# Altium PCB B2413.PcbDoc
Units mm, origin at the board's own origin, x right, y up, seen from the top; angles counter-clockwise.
Board outline 20.33 x 34.06 mm, 4 copper layers (Top Layer, Internal 1, Internal 2, Bottom Layer), stack 1.235 mm thick; 78 components, 60 nets, 384 pads, 246 vias.
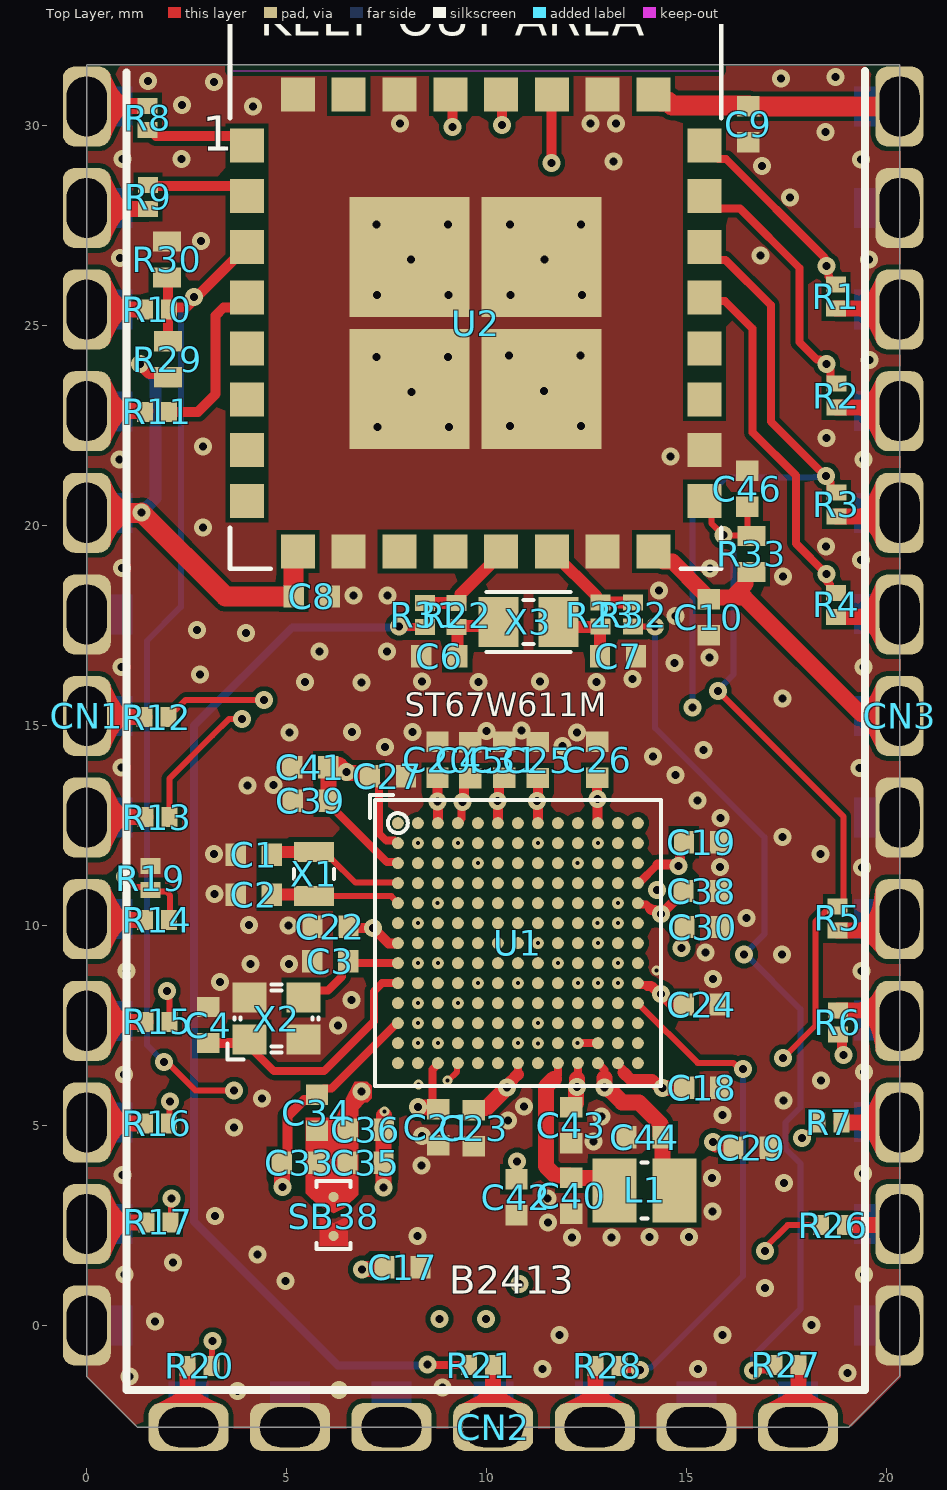
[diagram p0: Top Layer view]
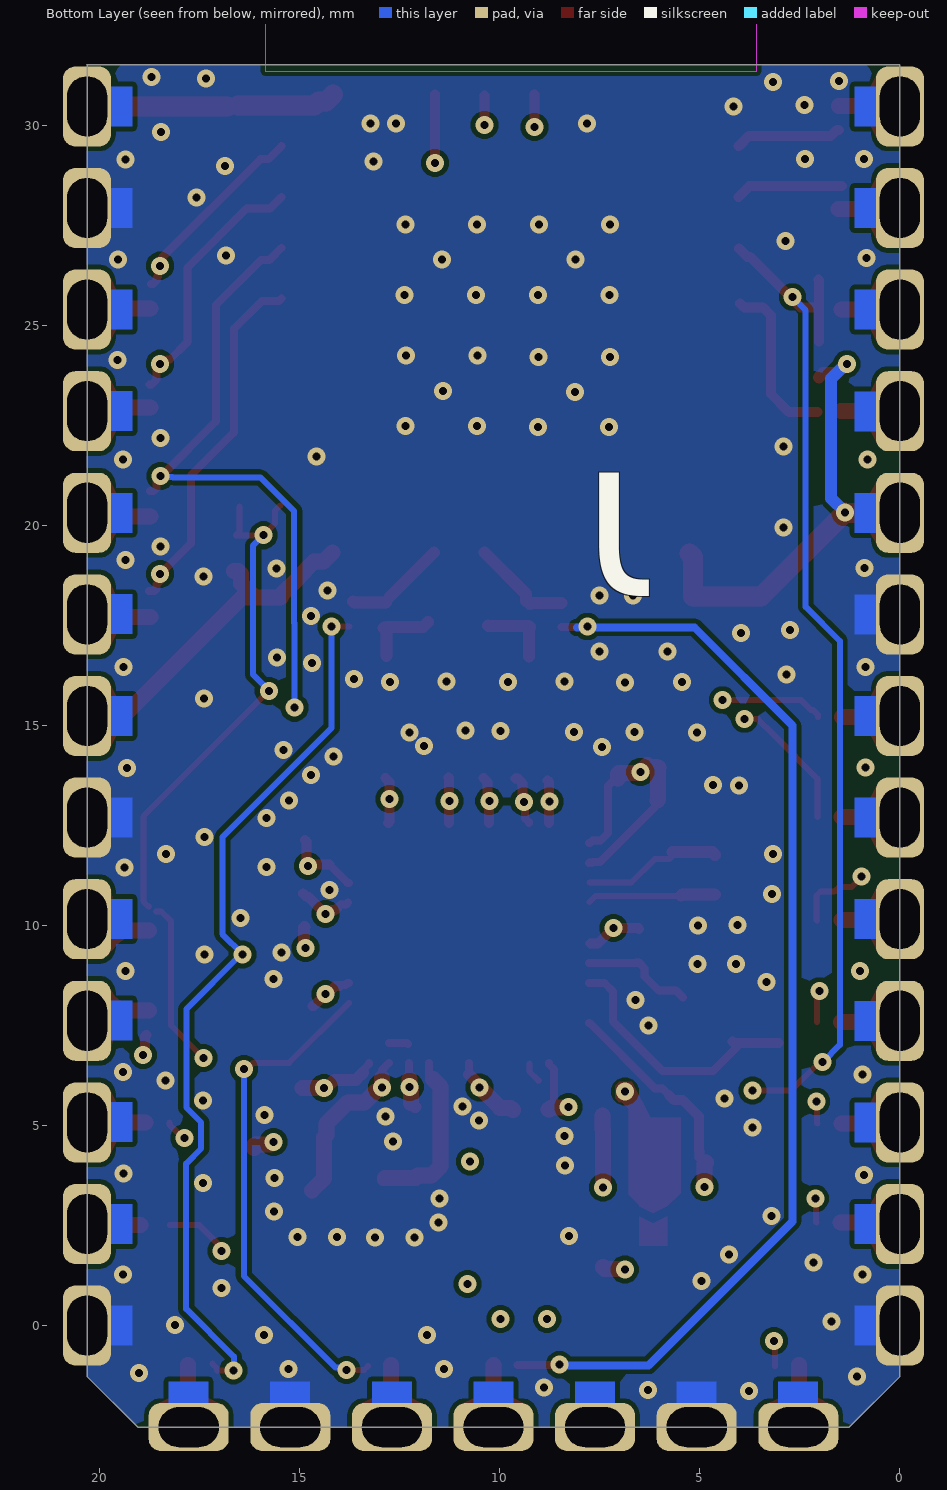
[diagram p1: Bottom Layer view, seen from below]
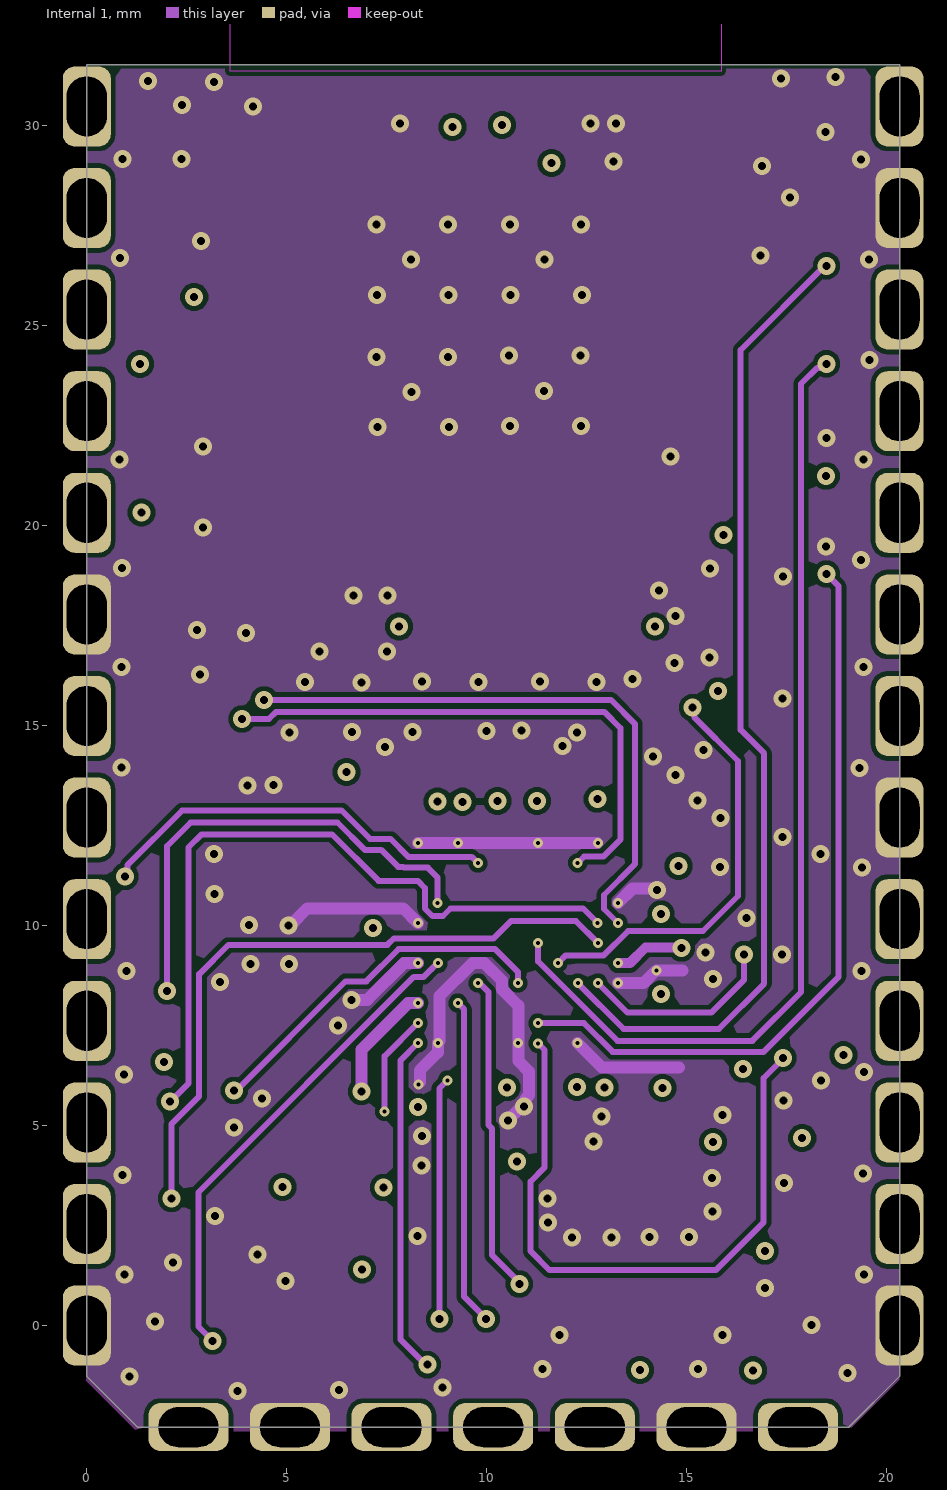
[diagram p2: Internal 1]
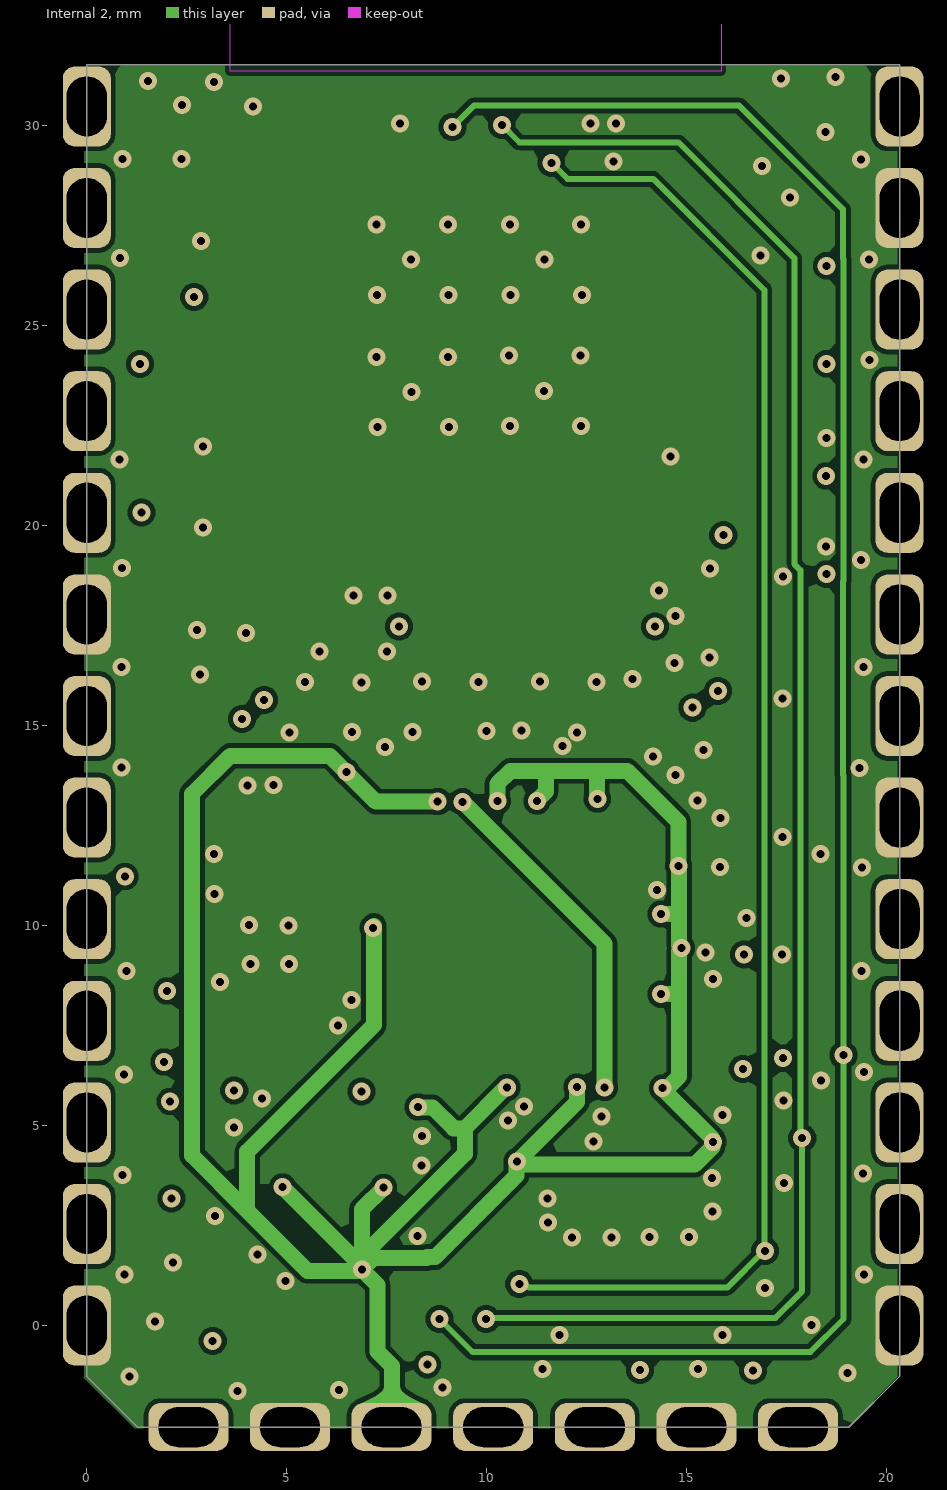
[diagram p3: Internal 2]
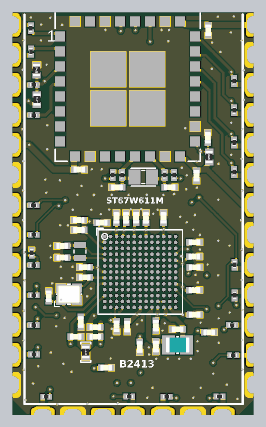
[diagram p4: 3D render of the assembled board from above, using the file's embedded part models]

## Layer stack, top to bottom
Top Solder: solder mask 0.0178, Solder Resist, Dk 3.2
Top Layer: signal copper 0.0406
Dielectric 1: core 0.0762, FR-4, Dk 3.7
Internal 1: signal copper 0.0305
Dielectric 3: prepreg 0.94, Dk 4.5
Internal 2: signal copper 0.0305
Dielectric 2: core 0.0762, Dk 3.7
Bottom Layer: signal copper 0.0406
Bottom Solder: solder mask 0.0178, Solder Resist, Dk 4.2

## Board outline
0,-1.27 1.27,-2.54 19.05,-2.54 20.32,-1.27 20.32,31.517 20.329,31.52 0,31.52 0,31.517

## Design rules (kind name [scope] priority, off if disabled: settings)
Clearance "RF Path 4" [InNet('NetJ1_1') vs InNet('GND')] p1: gap=0.18 ignorepadtopadclearanceinfootprint=FALSE
Clearance [All] p2: gap=0.12 ignorepadtopadclearanceinfootprint=FALSE
ComponentClearance [All] p1: gap=0.2 collisioncheckmode=3 verticalgap=0.2 showdistances=FALSE
HoleSize [All] p1: absolutevalues=TRUE maxlimit=10 minlimit=0.025 maxpercent=80.000 minpercent=20.000
HoleToHoleClearance [All] p1: gap=0.127 allowstackedmicrovias=TRUE
MinimumSolderMaskSliver [All] p1: minsoldermaskwidth=0.1
PlaneConnect [All] p1: planeconnectstyle=Relief reliefexpansion=0.508 reliefentries=4 reliefconductorwidth=0.21 reliefairgap=0.21
PolygonConnect Path_RF [InNet('NetC12_2')] p1: connectstyle=Direct reliefconductorwidth=0.254 reliefentries=4 polygonreliefangle="90 Angle" airgapwidth=0.254
PolygonConnect PolygonConnect_via [IsVia] p2: connectstyle=Direct reliefconductorwidth=0.254 reliefentries=4 polygonreliefangle="90 Angle" airgapwidth=0.254
PolygonConnect General [All] p3: connectstyle=Direct reliefconductorwidth=0.2 reliefentries=4 polygonreliefangle="90 Angle" airgapwidth=0.2
RoutingVias [All] p1: holewidth=0.3 width=0.8 viastyle="Through Hole" minholewidth=0.1 minwidth=0.25 maxholewidth=3.5 maxwidth=6.5
SilkToSilkClearance [All] p1 off: silktosilkclearance=0.2
SilkToSolderMaskClearance [IsPad] p1 off: minsilkscreentomaskgap=0.2 clearancetoexposedcopper=TRUE
SolderMaskExpansion [All] p1: expansion=0.102 istentingtop=FALSE
Width [All] p1: maxlimit=6 minlimit=0.1 preferedwidth=0.3 minimp=50.000000 maximp=50.000000 favimp=50.000000
23 further rules are at their usual default settings.

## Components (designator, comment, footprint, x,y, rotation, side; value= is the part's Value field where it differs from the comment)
C1 "Capacitor" C0402 4.17,11.769 r0 top value=1.8pF
C2 "Capacitor" C0402 4.172,10.774 r0 top value=1.8pF
C3 "Capacitor" C0402 6.086,9.11 r0 top value=6.8pF
C4 "Capacitor" C0402 3.036,7.514 r270 top value=6.8pF
C6 "Capacitor" C0402 8.817,16.729 r180 top value=5.1pF
C7 "Capacitor" C0402 13.282,16.734 r180 top value=5.1pF
C8 "Capacitor" C0402 5.621,18.227 r0 top value=10uF
C9 "Capacitor" C0402 16.542,30.033 r270 top value=10uF
C10 "Capacitor" C0402 15.548,17.705 r90 top value=10uF
C17 "Capacitor" C0402 7.894,1.455 r180 top value=10uF
C18 "Capacitor" C0402 15.388,5.943 r180 top value=100nF
C19 "Capacitor" C0402 15.381,12.079 r180 top value=100nF
C20 "Capacitor" C0402 8.769,14.142 r270 top value=100nF
C21 "Capacitor" C0402 8.786,4.956 r90 top value=100nF
C22 "Capacitor" C0402 6.093,9.971 r0 top value=100nF
C23 "Capacitor" C0402 9.679,4.936 r90 top value=100nF
C24 "Capacitor" C0402 15.376,8.026 r180 top value=100nF
C25 "Capacitor" C0402 11.27,14.138 r270 top value=100nF
C26 "Capacitor" C0402 12.759,14.145 r270 top value=100nF
C27 "Capacitor" C0402 7.53,13.732 r180 top value=100nF
C29 "Capacitor" C0402 16.618,4.449 r180 top value=4.7uF
C30 "Capacitor" C0402 15.395,9.963 r180 top value=100nF
C31 "Capacitor" C0402 10.435,14.145 r270 top value=100nF
C33 "Capacitor" C0402 5.328,4.073 r180 top value=1uF
C34 "Capacitor" C0402 5.755,5.322 r90 top value=100nF
C35 "Capacitor" C0402 6.968,4.071 r0 top value=1uF
C36 "Capacitor" C0402 6.972,4.891 r0 top value=100nF
C38 "Capacitor" C0402 15.369,10.863 r180 top value=100nF
C39 "Capacitor" C0402 5.6,13.116 r0 top value=100nF
C40 "Capacitor" C0402 12.115,3.245 r90 top value=100pF
C41 "Capacitor" C0402 5.588,13.953 r0 top value=10uF
C42 "Capacitor" C0402 10.743,3.208 r90 top value=10uF
C43 "Capacitor" C0402 12.113,5.011 r90 top value=100nF
C44 "Capacitor" C0402 13.944,4.706 r0 top value=2.2uF
C45 "Capacitor" C0402 9.588,14.137 r270 top value=2.2uF
C46 "Capacitor" C0402 16.51,20.92 r270 top value=100nF
CART-1 "Comment" Sheetbox_6L2S 32.282,-5.454 r0 top
CN1 "" STAMPS_HOLES_X13 0,2.54 r0 top
CN2 "" Stamps_holes_x7 2.532,-2.577 r0 top
CN3 "" STAMPS_HOLES_X13 20.32,27.94 r180 top
Designator1 "Comment" PCB_SPECIFICATIONS 32.657,17.871 r0 top
L1 "Inductor" L0805_H0P9 13.948,3.381 r0 top value=2.2uH
R1 "Resistor" R0201_H0P23 18.731,25.726 r270 top value=0R
R2 "Resistor" R0201_H0P23 18.738,23.247 r270 top value=0R
R3 "Resistor" R0201_H0P23 18.74,20.529 r270 top value=0R
R4 "Resistor" R0201_H0P23 18.733,18.017 r270 top value=0R
R5 "Resistor" R0201_H0P23 18.77,10.177 r270 top value=0R
R6 "Resistor" R0201_H0P23 18.779,7.58 r90 top value=0R
R7 "Resistor" R0201_H0P23 18.565,5.071 r0 top value=0R
R8 "Resistor" R0201_H0P23 1.521,30.195 r270 top value=0R
R9 "Resistor" R0201_H0P23 1.532,28.215 r90 top value=0R
R10 "Resistor" R0201_H0P23 1.758,25.407 r0 top value=0R
R11 "Resistor" R0201_H0P23 1.757,22.84 r0 top value=0R
R12 "Resistor" R0201_H0P23 1.745,15.211 r0 top value=0R
R13 "Resistor" R0201_H0P23 1.764,12.708 r0 top value=0R
R14 "Resistor" R0201_H0P23 1.757,10.134 r0 top value=0R
R15 "Resistor" R0201_H0P23 1.769,7.593 r0 top value=0R
R16 "Resistor" R0201_H0P23 1.759,5.056 r0 top value=0R
R17 "Resistor" R0201_H0P23 1.788,2.579 r0 top value=0R
R19 "Resistor" R0201_H0P23 1.597,11.186 r90 top value=100K
R20 "Resistor" R0201_H0P23 2.819,-1.005 r0 top value=0R
R21 "Resistor" R0201_H0P23 9.859,-0.987 r180 top value=0R
R22 "Resistor" R0201_H0P23 9.248,17.76 r270 top value=NM
R23 "Resistor" R0201_H0P23 12.845,17.773 r270 top value=NM
R26 "Resistor" R0201_H0P23 18.661,2.512 r0 top value=0R
R27 "Resistor" R0201_H0P23 17.492,-0.981 r180 top value=0R
R28 "Resistor" R0201_H0P23 13.021,-1.006 r0 top value=0R
R29 "Resistor" R0402 2.027,24.156 r270 top value=NM
R30 "Resistor" R0402 2.01,26.653 r270 top value=33K
R31 "Resistor" R0201_H0P23 8.459,17.768 r90 top value=0R
R32 "Resistor" R0201_H0P23 13.652,17.773 r270 top value=0R
R33 "Resistor" R0402 16.62,19.289 r270 top value=33K
SB38 "SB_ON" SOLDER-BRIDGE_R0402-0R 6.17,2.767 r270 top value=0R
U1 "STM32U575AII6QU" ICC_UFBGA169_7X7_P050 10.778,9.562 r0 top value=STM32U575AII6Q
U2 "STM32WW611MNA6BT" STM32WW611MNA6B 4.036,29.502 r0 top
X1 "XTAL_2_PINS" CRY_NX1610SE_2P 5.681,11.287 r90 top value=32.768kHz
X2 "XTAL_4_PINS" CRY_NX2016SA_4P 4.746,7.673 r0 top value=16MHz
X3 "XTAL_2_PINS" CRY_NX2012SA_2P 11.043,17.593 r180 top value=32.768KHz

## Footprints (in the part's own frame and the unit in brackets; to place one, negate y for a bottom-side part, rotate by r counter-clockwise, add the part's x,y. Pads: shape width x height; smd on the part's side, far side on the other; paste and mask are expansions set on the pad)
C0402 [mm]
  rect 0.51x0.56 smd mask+0.05: 1(-0.45,0) 2(0.45,0)
  body extent -0.5,-0.3 0.5,0.3, height 0.4
CRY_NX1610SE_2P [mm] "MCD-02291"
  rect 0.5x1 smd mask+0.05: 1(-0.55,0) 2(0.55,0)
  silkscreen extent -0.13,-0.5 0.13,0.5, body extent -0.8,-0.5 0.8,0.5, height 0.45
CRY_NX2012SA_2P [mm]
  rect 1x1.25 smd mask+0.05: 1(-0.75,0) 2(0.75,0)
  silkscreen extent -1.05,-0.75 1.05,0.75, body extent -1.05,-0.63 1.05,0.63, height 0.6
CRY_NX2016SA_4P [mm]
  rect 0.85x0.75 smd mask+0.05: 1(-0.675,-0.525) 2(0.675,-0.525) 3(0.675,0.525) 4(-0.675,0.525)
  silkscreen extent -1.22,-1.02 1.05,0.85, body extent -1.05,-0.85 1.05,0.85, height 0.7
ICC_UFBGA169_7X7_P050 [mm]
  round 0.3 smd mask+0.05: A1(-3,3) A2(-2.5,3) A3(-2,3) A4(-1.5,3) A5(-1,3) A6(-0.5,3) A7(0,3) A8(0.5,3) A9(1,3) A10(1.5,3) A11(2,3) A12(2.5,3) A13(3,3) B1(-3,2.5) B2(-2.5,2.5) B3(-2,2.5) B4(-1.5,2.5) B5(-1,2.5) B6(-0.5,2.5) B7(0,2.5) B8(0.5,2.5) B9(1,2.5) B10(1.5,2.5) B11(2,2.5) B12(2.5,2.5) B13(3,2.5) C1(-3,2) C2(-2.5,2) C3(-2,2) C4(-1.5,2) C5(-1,2) C6(-0.5,2) C7(0,2) C8(0.5,2) C9(1,2) C10(1.5,2) C11(2,2) C12(2.5,2) C13(3,2) D1(-3,1.5) D2(-2.5,1.5) D3(-2,1.5) D4(-1.5,1.5) D5(-1,1.5) D6(-0.5,1.5) D7(0,1.5) D8(0.5,1.5) D9(1,1.5) D10(1.5,1.5) D11(2,1.5) D12(2.5,1.5) D13(3,1.5) E1(-3,1) E2(-2.5,1) E3(-2,1) E4(-1.5,1) E5(-1,1) E6(-0.5,1) E7(0,1) E8(0.5,1) E9(1,1) E10(1.5,1) E11(2,1) E12(2.5,1) E13(3,1) F1(-3,0.5) F2(-2.5,0.5) F3(-2,0.5) F4(-1.5,0.5) F5(-1,0.5) F6(-0.5,0.5) F7(0,0.5) F8(0.5,0.5) F9(1,0.5) F10(1.5,0.5) F11(2,0.5) F12(2.5,0.5) F13(3,0.5) G1(-3,0) G2(-2.5,0) G3(-2,0) G4(-1.5,0) G5(-1,0) G6(-0.5,0) G7(0,0) G8(0.5,0) G9(1,0) G10(1.5,0) G11(2,0) G12(2.5,0) G13(3,0) H1(-3,-0.5) H2(-2.5,-0.5) H3(-2,-0.5) H4(-1.5,-0.5) H5(-1,-0.5) H6(-0.5,-0.5) H7(0,-0.5) H8(0.5,-0.5) H9(1,-0.5) H10(1.5,-0.5) H11(2,-0.5) H12(2.5,-0.5) H13(3,-0.5) J1(-3,-1) J2(-2.5,-1) J3(-2,-1) J4(-1.5,-1) J5(-1,-1) J6(-0.5,-1) J7(0,-1) J8(0.5,-1) J9(1,-1) J10(1.5,-1) J11(2,-1) J12(2.5,-1) J13(3,-1) K1(-3,-1.5) K2(-2.5,-1.5) K3(-2,-1.5) K4(-1.5,-1.5) K5(-1,-1.5) K6(-0.5,-1.5) K7(0,-1.5) K8(0.5,-1.5) K9(1,-1.5) K10(1.5,-1.5) K11(2,-1.5) K12(2.5,-1.5) K13(3,-1.5) L1(-3,-2) L2(-2.5,-2) L3(-2,-2) L4(-1.5,-2) L5(-1,-2) L6(-0.5,-2) L7(0,-2) L8(0.5,-2) L9(1,-2) L10(1.5,-2) L11(2,-2) L12(2.5,-2) L13(3,-2) M1(-3,-2.5) M2(-2.5,-2.5) M3(-2,-2.5) M4(-1.5,-2.5) M5(-1,-2.5) M6(-0.5,-2.5) M7(0,-2.5) M8(0.5,-2.5) M9(1,-2.5) M10(1.5,-2.5) M11(2,-2.5) M12(2.5,-2.5) M13(3,-2.5) N1(-3,-3) N2(-2.5,-3) N3(-2,-3) N4(-1.5,-3) N5(-1,-3) N6(-0.5,-3) N7(0,-3) N8(0.5,-3) N9(1,-3) N10(1.5,-3) N11(2,-3) N12(2.5,-3) N13(3,-3)
  silkscreen extent -3.7,-3.57 3.57,3.7, body extent -3.57,-3.57 3.57,3.57, height 0.61
L0805_H0P9 [mm]
  rect 1.1x1.6 smd mask+0.05: 1(-0.75,0) 2(0.75,0)
  silkscreen extent -0.08,-0.7 0.08,0.7, body extent -1.07,-0.7 1.07,0.7, height 1.2
PCB_SPECIFICATIONS [mm]
R0201_H0P23 [mm]
  rect 0.4x0.5 smd mask+0.05: 1(-0.3,0) 2(0.3,0)
  body extent -0.32,-0.17 0.32,0.17, height 0.26
R0402 [mm]
  rect 0.51x0.7 smd mask+0.05: 1(-0.45,0) 2(0.45,0)
  body extent -0.52,-0.3 0.52,0.3, height 0.4
Sheetbox_6L2S [mil] "Sheetbox 6 layers / 2 silkscreens"
  round 20 on Mech16: 1(813.5,208.05) 1(2736.63,208.05)
SOLDER-BRIDGE_R0402-0R [mil] "MCD-01619"
  round 10 smd paste-393.7: 1(-17.72,0) 2(20.67,0)
  Top Layer region: 1.48,13.78 8.37,0 1.48,-13.78 30.51,-13.78 30.51,13.78
  Top Layer region: -30.51,-13.78 -30.51,13.78 -8.37,13.78 -1.48,0 -8.37,-13.78
  silkscreen extent -33,-17 33,17, body extent -20,-12 20,12, height 14
Stamps_holes_x7 [mm]
  rrect50% 2x1.2 hole 1 slot 1.5 at 0 deg mask+0.102: 1(0.008,0.037) 2(2.548,0.037) 3(5.088,0.037) 4(7.628,0.037) 5(10.168,0.037) 6(12.708,0.037) 7(15.248,0.037)
  Bottom Layer region: 8.132,-0.024 8.132,1.176 7.132,1.176 7.132,-0.024
  Bottom Layer region: 5.592,-0.024 5.592,1.176 4.592,1.176 4.592,-0.024
  Bottom Layer region: 3.052,-0.025 3.052,1.175 2.052,1.175 2.052,-0.025
  Bottom Layer region: 0.512,-0.024 0.512,1.176 -0.488,1.176 -0.488,-0.024
  Bottom Layer region: 10.672,-0.024 10.672,1.176 9.672,1.176 9.672,-0.024
  Bottom Layer region: 13.212,-0.024 13.212,1.176 12.212,1.176 12.212,-0.024
  Bottom Layer region: 15.752,-0.024 15.752,1.176 14.752,1.176 14.752,-0.024
STAMPS_HOLES_X13 [mm]
  rrect50% 1.2x2 hole 1 slot 1.5 at 90 deg mask+0.102: 1(0,27.94) 2(0,25.4) 3(0,22.86) 4(0,20.32) 5(0,17.78) 6(0,15.24) 7(0,12.7) 8(0,10.16) 9(0,7.62) 10(0,5.08) 11(0,2.54) 12(0,0) 13(0,-2.54)
  Bottom Layer region: -0.062,-3.04 1.138,-3.04 1.138,-2.04 -0.062,-2.04
  Bottom Layer region: -0.062,19.817 1.138,19.817 1.138,20.817 -0.062,20.817
  Bottom Layer region: -0.062,22.357 1.138,22.357 1.138,23.357 -0.062,23.357
  Bottom Layer region: -0.062,24.897 1.138,24.897 1.138,25.897 -0.062,25.897
  Bottom Layer region: -0.062,27.437 1.138,27.437 1.138,28.437 -0.062,28.437
  Bottom Layer region: -0.062,17.277 1.138,17.277 1.138,18.277 -0.062,18.277
  Bottom Layer region: -0.062,14.737 1.138,14.737 1.138,15.737 -0.062,15.737
  Bottom Layer region: -0.062,12.197 1.138,12.197 1.138,13.197 -0.062,13.197
  Bottom Layer region: -0.062,9.657 1.138,9.657 1.138,10.657 -0.062,10.657
  Bottom Layer region: -0.062,7.12 1.138,7.12 1.138,8.12 -0.062,8.12
  Bottom Layer region: -0.062,4.58 1.138,4.58 1.138,5.58 -0.062,5.58
  Bottom Layer region: -0.062,2.04 1.138,2.04 1.138,3.04 -0.062,3.04
  Bottom Layer region: -0.062,-0.5 1.138,-0.5 1.138,0.5 -0.062,0.5
STM32WW611MNA6B [mm]
  rect 0.85x0.85 smd mask+0.05: 1(-0.027,0.005) 2(-0.027,-1.265) 3(-0.027,-2.535) 4(-0.027,-3.805) 5(-0.027,-5.075) 6(-0.027,-6.345) 7(-0.027,-7.615) 8(-0.027,-8.885) 9(1.243,-10.155) 10(2.513,-10.155) 11(3.783,-10.155) 12(5.053,-10.155) 13(6.323,-10.155) 14(7.593,-10.155) 15(8.863,-10.155) 16(10.133,-10.155) 17(11.403,-8.885) 18(11.403,-7.615) 19(11.403,-6.345) 20(11.403,-5.075) 21(11.403,-3.805) 22(11.403,-2.535) 23(11.403,-1.265) 24(11.403,0.005) 25(10.133,1.275) 26(8.863,1.275) 27(7.593,1.275) 28(6.323,1.275) 29(5.053,1.275) 30(3.783,1.275) 31(2.513,1.275) 32(1.243,1.275)
  rect 3x3 smd mask+0.05: 33(4.038,-2.79) 34(4.038,-6.09) 35(7.338,-6.09) 36(7.338,-2.79)
  Keep-Out Layer region: -0.452,6.7 11.828,6.7 11.828,1.86 -0.452,1.86
  silkscreen extent -0.45,-10.58 11.83,6.7, body extent -0.46,-10.58 11.83,6.7, height 1.4

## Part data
C1 C2: library part MCD-02995, "Capacitor, MLCC, 1.8pF, 50V, C0G, +/-0.25pF, 0402, T=0.5mm", Manufacturer=MURATA, Manufacturer_Part_Number=GRM1555C1H1R8CA01, Package=0402
C3 C4: library part MCD-00674, "Capacitor, MLCC, 6.8pF, 50V, NPO, +/-0.25pF, 0402, T=0.5mm", Manufacturer=YAGEO, Manufacturer_Part_Number=CC0402CRNPO9BN6R8, Package=0402
C6 C7: library part MCD-00003, "Capacitor, MLCC, 5.1pF, 50V, NPO, +/-0.25pF, 0402, T=0.5mm", Manufacturer=YAGEO, Manufacturer_Part_Number=CC0402CRNPO9BN5R1, Package=0402
C8 C9 C10 C17 C41 C42: library part MCD-01532, "Capacitor, MLCC, 10uF, 10V, X5R, +/-20%, 0402, T=0.5mm", Manufacturer=MURATA, Manufacturer_Part_Number=GRM155R61A106ME11, Package=0402
C18 C19 C20 C21 C22 C23 C24 C25 C26 C27 C30 C31 C34 C36 C38 C39 C43: library part MCD-00102, "Capacitor, MLCC, 100nF, 16V, X7R, +/-10%, 0402, T=0.5mm", Manufacturer=YAGEO, Manufacturer_Part_Number=CC0402KRX7R7BB104, Package=0402
C29: library part MCD-03816, "Capacitor, MLCC, 4.7uF, 6V3, X6S, +/-22%, 0402, T=0.5mm", Manufacturer=MURATA, Manufacturer_Part_Number=GRM155C80J475ME01, Package=0402
C33 C35: library part MCD-00010, "Capacitor, MLCC, 1uF, 16V, X5R, +/-10%, 0603, T=0.8mm", Manufacturer=YAGEO, Manufacturer_Part_Number=CC0603KRX5R7BB105, Package=0603
C40: library part MCD-00205, "Capacitor, MLCC, 100pF, 50V, NPO, +/-5%, 0402, T=0.5mm", Manufacturer=YAGEO, Manufacturer_Part_Number=CC0402JRNPO9BN101, Package=0402
C44 C45: library part MCD-01823, "Capacitor, MLCC, 2.2uF, 6V3, X5R,+/-10%, 0402, T=0.5mm", Manufacturer=MURATA, Manufacturer_Part_Number=GRM155R60J225KE95D, Package=0402
C46: library part MCD-00006, "Capacitor, MLCC, 100nF, 16V, X7R, +/-10%, 0402, T=0.5mm", Manufacturer=YAGEO, Manufacturer_Part_Number=CC0402KRX7R7BB104, Package=0402
CN1 CN3: library part hole_2_54_x13
CN2: library part hole_2_54_x7
L1: library part MCD-01060, "Inductor, 2.2uH, 20%, Isat 0.7A, DCR 0.156Ohm, 0805", Manufacturer=MURATA, Manufacturer_Part_Number=LQM21PN2R2MGH, Package=L0805
R1 R2 R3 R4 R5 R6 R7 R8 R9 R10 R11 R12 R13 R14 R15 R16 R17 R20 R21 R22 R23 R26 R27 R28 R31 R32: library part MCD-02450, "Resistor, 0R, 0201, 1/20W", Manufacturer=YAGEO, Manufacturer_Part_Number=RC0201JR-070RP, Package=0201
R19: library part MCD-03041, "Resistor, 100K, 0201, +/-1%, 1/20W", Manufacturer=YAGEO, Manufacturer_Part_Number=RC0201FR-07100KL, Package=0201
R29 R30 R33: library part MCD-00258, "Resistor, 33K, 0402, +/-1%, 1/16W", Manufacturer=YAGEO, Manufacturer_Part_Number=RC0402FR-0733KL, Package=0402
SB38: library part MCD-01618, "Resistor, 0R, SB0402, 5%, 0.063W", Manufacturer=YAGEO, Manufacturer_Part_Number=RC0402JR-070RL, Package=0402
U1: library part MCD-01928, "MCU, ARM Cortex-M33 32-bit, 2MB Flash, 786KB RAM, With Crypto, SMPS", Manufacturer=STMICROELECTRONICS, Manufacturer_HQ_COO=EU, Manufacturer_Part_Number=STM32U575AII6Q, Package=BGA-169
U2: library part STM32WW6QM, "STM32WW6QMCNH"
X1: library part MCD-02291, "Crystal, 32.768kHz, 9pF, +/-20ppm, 70KR, 1.6x1mm", Manufacturer=NDK, Manufacturer_Part_Number=NX1610SE-32.768KHZ-EXS00A-MU01499, Package=1.6x1mm
X2: library part MCD-01476, "Crystal, 16 MHz, 8pF, +/-20ppm, 200R, 2x1.6mm", Manufacturer=NDK, Manufacturer_Part_Number=NX2016SA-16MHZ-EXS00A-CS07826, Package=2x1.6mm
X3: library part MCD-01479, "Crystal, 32.768kHz, 6pF, +/-20ppm, 80K, 2.05x1.2mm", Manufacturer=NDK, Manufacturer_Part_Number=NX2012SA-32.768KHZ-EXS00A-MU00527, Package=2.05x1.2mm

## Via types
v1: diameter 0.45, hole 0.2, Top Layer to Bottom Layer, tented both sides, 211 vias
v2: diameter 0.25, hole 0.1, Top Layer to Internal 1, tented top, 35 vias

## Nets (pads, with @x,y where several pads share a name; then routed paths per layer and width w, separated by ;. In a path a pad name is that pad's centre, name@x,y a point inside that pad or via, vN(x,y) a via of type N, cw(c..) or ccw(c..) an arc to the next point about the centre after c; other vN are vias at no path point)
16M_U5_IN: C3.2 U1.H1 X2.3 | length 2.8
  Top Layer w0.2: X2.3 5.598,8.375 6.029,8.375 6.381,8.727 6.381,8.93 6.525,9.074 C3.2@6.599,9.074 ; C3.2@6.599,9.062 U1.H1
16M_U5_OUT: C4.2 U1.J1 X2.1 | length 6.5
  Top Layer w0.2: X2.1@4.062,6.976 4.676,6.362 5.936,6.362 7.176,7.602 7.176,8.355 7.379,8.558 ; 7.379,8.562 U1.J1
  Top Layer w0.25: C4.2 4.149,7.064 X2.1@4.182,7.096
32k_U5_IN: C1.2 U1.D1 X1.2 | length 3.5
  Top Layer w0.15: X1.2@5.639,11.795 5.771,11.662 6.127,11.662 6.713,11.077 U1.D1@7.762,11.077
  Top Layer w0.3: C1.2 4.689,11.837 X1.2
32k_U5_OUT: C2.2 U1.E1 X1.1 | length 3.1
  Top Layer w0.15: X1.1@5.596,10.737 X1.1 7.614,10.737 U1.E1@7.764,10.587
  Top Layer w0.3: C2.2 5.448,10.774 X1.1@5.474,10.747
AGND: C33.1 C34.1 C35.1 C36.1 SB38.1 U1.K2 | length 2.9
  Internal 1 w0.3: v1(6.871,5.855) 6.871,6.9 8.036,8.065 v2(8.276,8.065)
BOOT0_U5: R14.2 R19.1 U1.C5 | length 12.1
  Top Layer w0.15: v1@0.971,11.199 1.21,10.96 1.523,10.96 R19.1 1.631,10.852 1.984,10.852 2.086,10.751 2.086,10.133 R14.2@2.078,10.125
  Internal 1 w0.15: v1(0.959,11.23) 1.016,11.287 1.016,11.509 2.385,12.877 6.372,12.877 7.086,12.163 7.595,12.163 8.041,11.717 9.625,11.717 v2(9.78,11.561)
"BOOT_WW6 / JTDO": R10.2 R29.1 R30.2 U1.J7 U2.3 | length 35.1
  Top Layer w0.15: v1(1.931,6.586) 2.011,6.586 2.716,5.88 v1(3.686,5.88)
  Top Layer w0.25: R29.1 2.027,26.14 R30.2@2.039,26.152 ; R10.2@2.058,25.457 2.488,25.457 3.75,26.718 3.812,26.718 U2.3@4.025,26.931
  Internal 1 w0.15: v1@3.685,5.822 6.47,8.607 6.989,8.607 7.794,9.412 10.21,9.412 10.778,8.844 v2(10.778,8.564)
  Bottom Layer w0.15: v1(1.931,6.586) 1.5,7.017 1.5,17.115 2.354,17.969 2.354,25.379 v1(2.687,25.711)
CHIP_EN_U5: C46.2 R5.1 R33.1 U1.M8 U2.17 | length 33.7
  Top Layer w0.15: U2.17@15.49,20.507 15.617,20.38 15.617,20.055 15.919,19.753 16.6,19.753 16.603,19.756 16.515,19.844 C46.2@16.515,20.474 ; v1(15.778,15.866) 18.915,12.729 18.915,10.602 18.79,10.477 R5.1 ; v1(17.409,6.69) 18.219,7.5 18.219,10.107 18.464,10.352 R5.1@18.595,10.352
  Internal 1 w0.15: v2(11.281,7.056) 11.446,6.89 11.446,3.953 11.096,3.602 11.096,1.859 11.57,1.385 15.727,1.385 16.922,2.581 16.922,6.188 v1@17.412,6.677
  Bottom Layer w0.15: v1(15.778,15.866) 15.778,15.883 16.167,16.271 16.167,19.505 v1(15.913,19.759)
Device_Ready_U5: R4.1 U1.L8 U2.21 | length 27.7
  Top Layer w0.2: U2.21@15.461,25.673 15.517,25.617 15.951,25.617 16.646,24.922 16.646,22.331 17.728,21.249 17.728,19.55 v1(18.494,18.785) ; v1@18.41,18.701 18.41,18.699 18.583,18.525 18.583,18.417 18.638,18.362 R4.1@18.77,18.362
  Internal 1 w0.15: v2(11.279,7.562) 12.43,7.562 13.15,6.842 16.92,6.842 18.796,8.718 18.796,18.483 v1(18.494,18.785)
Device_Wakeup_U5: R27.2 R32.2 U1.J11 | length 27.4
  Top Layer w0.15: R32.2@13.756,17.473 v1(14.206,17.473) ; v1(16.656,-1.118) 17.067,-1.118 17.067,-1.073 R27.2@17.189,-0.951
  Internal 1 w0.15: v2(12.781,8.56) 13.518,7.822 15.614,7.822 16.434,8.643 v1(16.434,9.279)
  Bottom Layer w0.15: v1(14.206,17.473) 14.206,14.944 16.938,12.212 16.938,9.783 v1(16.434,9.279) 16.473,9.279 17.841,7.911 17.841,5.45 17.467,5.076 17.467,4.425 17.845,4.047 17.845,0.417 16.651,-0.777 16.651,-1.113 v1(16.656,-1.118)
Ext_32k_U5: R21.2 R31.1 U1.M2 | length 36.4
  Top Layer w0.2: v1@7.772,17.44 7.801,17.468 R31.1 ; v1(8.513,-0.98) 8.525,-0.991 9.555,-0.991 R21.2
  Internal 1 w0.15: v2(8.279,7.063) 7.848,6.632 7.848,-0.354 8.474,-0.98 v1(8.513,-0.98)
  Bottom Layer w0.2: 8.067,17.456 5.141,17.456 2.684,14.999 2.684,2.603 6.282,-0.995 8.497,-0.995 v1(8.513,-0.98)
  other v1: 7.811,17.475
GND: C1.1 C2.1 C3.1 C4.1 C6.2 C7.1 C8.2 C9.2 C10.1 C17.1 C18.1 C19.1 C20.1 C21.1 C22.1 C23.1 C24.1 C25.1 C26.1 C27.1 C29.1 C30.1 C31.1 C38.1 C39.1 C40.1 C41.1 C42.1 C43.1 C44.1 C45.1 C46.1 CN1.6 CN1.13 CN2.2 CN2.6 CN3.1 CN3.6 CN3.12 R19.2 R30.1 SB38.2 U1.B2 U1.B4 U1.B8 U1.B11 U1.E12 U1.F2 U1.H2 U1.J12 U1.M3 U1.M7 U1.M10 U1.M11 U2.10 U2.15 U2.18 U2.26 U2.30 U2.32 U2.33 U2.34 U2.35 U2.36 X2.2 X2.4 | length 24.7
  Top Layer w0.2: U1.M10@12.293,7.038 12.317,7.062 U1.M11
  Internal 1 w0.3: v1@5.07,10.074 5.111,10.033 5.119,10.033 5.517,10.432 7.908,10.432 v2(8.276,10.064) ; v1(6.614,8.144) 7.013,8.144 7.931,9.062 v2(8.28,9.062) ; v2(8.276,12.066) 12.759,12.066 v2@12.761,12.068 ; v2@8.327,6.09 8.327,6.38 8.779,6.831 v2(8.779,7.063) 8.825,7.11 8.825,8.243 9.642,9.061 9.943,9.061 10.383,8.621 10.383,8.4 10.787,7.996 10.787,6.616 11.057,6.346 11.057,5.76 10.963,5.666 10.963,5.504 10.905,5.447 10.845,5.447 10.527,5.129 v1(10.527,5.124) ; v2(12.273,7.062) 12.878,6.457 14.808,6.457 ; v2(13.276,10.559) 13.642,10.925 v1@14.29,10.925 ; v2(13.28,8.564) 13.923,8.564 v2(14.238,8.879) 14.896,8.879
  other v1: 3.769,-1.639 6.303,-1.611 8.895,-1.552 1.071,-1.269 19.022,-1.182 11.393,-1.087 15.284,-1.086 11.824,-0.242 15.893,-0.237 18.12,0.02 1.709,0.102 16.959,0.945 4.964,1.111 0.938,1.277 19.425,1.273 2.161,1.573 4.273,1.779 12.132,2.201 13.118,2.202 14.074,2.209 15.059,2.21 8.27,2.233 11.531,2.573 3.209,2.741 15.643,2.857 11.516,3.182 17.425,3.57 15.633,3.683 0.894,3.769 19.408,3.8 8.373,4.001 12.67,4.601 8.385,4.744 3.681,4.948 12.863,5.229 15.891,5.269 10.934,5.476 17.421,5.624 4.379,5.674 18.355,6.126 0.932,6.281 19.426,6.342 6.287,7.495 3.331,8.59 15.657,8.667 0.992,8.863 19.367,8.862 4.093,9.041 5.055,9.038 17.385,9.272 15.463,9.32 5.049,10.005 4.059,10.011 16.488,10.189 3.198,10.786 14.26,10.887 15.835,11.461 19.386,11.456 3.175,11.783 18.344,11.795 17.388,12.21 15.839,12.693 15.271,13.126 4.018,13.507 4.67,13.518 14.719,13.759 19.321,13.941 0.864,13.957 14.16,14.231 15.416,14.386 7.452,14.46 11.897,14.488 5.068,14.831 8.144,14.834 12.261,14.829 6.635,14.837 9.988,14.862 10.863,14.874 17.396,15.674 6.87,16.078 5.453,16.084 8.38,16.099 9.797,16.094 11.331,16.099 12.748,16.094 13.646,16.159 2.833,16.277 0.864,16.467 19.417,16.467 14.695,16.563 15.574,16.705 5.814,16.85 7.509,16.849 3.978,17.313 2.752,17.387 14.724,17.741 6.669,18.246 7.513,18.251 14.304,18.374 17.408,18.723 0.879,18.942 15.579,18.925 19.361,19.133 18.482,19.473 2.911,19.957 0.815,21.65 19.42,21.654 14.588,21.731 2.91,21.972 18.488,22.194 7.267,22.458 9.052,22.458 10.577,22.487 12.362,22.487 8.117,23.341 11.428,23.37 19.564,24.136 7.25,24.219 9.035,24.219 10.56,24.247 12.345,24.247 7.261,25.763 9.046,25.763 10.594,25.763 12.379,25.763 8.112,26.646 11.445,26.646 19.553,26.65 0.835,26.685 16.846,26.757 2.855,27.116 7.244,27.524 9.029,27.524 10.577,27.524 12.362,27.524 17.583,28.199 16.876,28.99 13.164,29.107 19.361,29.149 0.897,29.163 2.371,29.164 18.467,29.843 12.592,30.049 13.229,30.045 7.827,30.052 4.16,30.477 2.386,30.511 1.527,31.109 3.177,31.094 17.352,31.182 18.713,31.208
  other v2: 8.297,6.024 10.777,7.063 9.275,12.062 11.278,12.066 12.777,12.066
JTCK: R9.2 U2.2 | length 2.7
  Top Layer w0.25: R9.2@1.443,28.489 3.755,28.489 U2.2@4.031,28.213
JTDI: R11.2 U2.4 | length 4.2
  Top Layer w0.25: R11.2 2.777,22.84 3.224,23.287 3.224,25.255 3.418,25.448 3.891,25.448 U2.4@3.994,25.551
JTMS: R8.2 U2.1 | length 2.7
  Top Layer w0.25: R8.2 1.571,29.895 1.73,29.736 3.778,29.736 U2.1@4.031,29.483
LPUART1_RX: R2.1 U1.G8 U2.23 | length 30.9
  Top Layer w0.2: U2.23@15.461,28.213 15.749,27.924 16.333,27.924 17.813,26.444 17.813,24.585 18.253,24.146 18.325,24.146 18.426,24.045 v1(18.494,24.045) 18.494,23.977 18.588,23.883 18.588,23.647 18.714,23.522 R2.1@18.762,23.522
  Internal 1 w0.15: v2(11.28,9.562) 11.28,9.106 13.269,7.117 16.638,7.117 17.857,8.335 17.857,23.545 18.258,23.945 18.313,23.945 18.413,24.045 v1(18.494,24.045)
"LPUART1_TX/ HostWakeup": R3.1 U1.H9 U2.22 | length 26.6
  Top Layer w0.2: U2.22@15.461,26.943 15.762,26.642 15.972,26.642 17.102,25.512 17.102,22.604 18.463,21.243 v1(18.486,21.243) 18.486,21.175 18.59,21.071 18.59,20.929 18.657,20.862 R3.1@18.753,20.862
  Internal 1 w0.15: v2@11.806,9.086 11.966,9.246 12.914,9.246 13.533,9.864 15.407,9.864 16.282,10.739 16.282,14.114 15.197,15.198 15.197,15.389 v1(15.14,15.446)
  Bottom Layer w0.15: v1(15.14,15.446) 15.14,17.563 15.144,17.567 15.144,20.361 15.987,21.205 18.172,21.205 18.18,21.213 18.456,21.213 v1(18.486,21.243)
  other v2: 11.776,9.065
NetC6_1: C6.1 R22.2 X3.2 | length 1.7
  Top Layer w0.3: R22.2 9.281,17.493 10.284,17.493 X3.2@10.294,17.502 ; C6.1 9.267,17.41 R22.2@9.271,17.41
NetC7_2: C7.2 R23.2 X3.1 | length 1.9
  Top Layer w0.3: X3.1 11.919,17.466 R23.2@12.845,17.466 ; C7.2 12.832,17.423 12.854,17.444 R23.2@12.916,17.444
NetC40_2: C40.2 L1.1 U1.N9 | length 4.3
  Top Layer w0.2: 11.678,6.165 11.778,6.265 U1.N9
  Top Layer w0.3: L1.1@12.872,3.692 L1.1@12.923,3.641
  Top Layer w0.4: 11.678,6.165 11.48,5.966 11.48,3.984 11.714,3.75 12.058,3.75 12.115,3.692 L1.1@12.872,3.692
NetC44_2: C44.2 C45.2 L1.2 U1.A4 U1.N11 | length 13.9
  Top Layer w0.2: U1.A4 9.278,12.589 9.369,12.68 v1@9.369,13.095 ; U1.N11 12.948,6.392 12.948,6.185
  Top Layer w0.25: v1@9.395,13.149 9.434,13.188 9.434,13.557 9.55,13.673 C45.2@9.612,13.673
  Top Layer w0.4: v1(12.948,5.955) 12.948,6.185 ; v1@13.108,5.855 13.383,5.579 13.804,5.579 14.339,5.044 14.339,4.761 C44.2 14.394,3.685 L1.2
  Internal 2 w0.4: v1(9.395,13.095) 12.948,9.541 v1(12.948,5.955)
NetCN1_1: CN1.1 R8.1 | length 1.5
  Top Layer w0.4: CN1.1@0.015,30.495 R8.1
NetCN1_2: CN1.2 R9.1 | length 1.5
  Top Layer w0.4: CN1.2@0.025,27.915 R9.1
NetCN1_3: CN1.3 R10.1 | length 1.5
  Top Layer w0.25: R10.1@1.455,25.4 R10.1@1.474,25.419
  Top Layer w0.4: CN1.3 R10.1@1.455,25.4
NetCN1_4: CN1.4 R11.1 | length 1.5
  Top Layer w0.25: R11.1@1.467,22.86 R11.1@1.497,22.83
  Top Layer w0.4: CN1.4 R11.1@1.467,22.86
NetCN1_7: CN1.7 R12.1 | length 1.3
  Top Layer w0.25: CN1.7@0.146,15.185 CN1.7@0.172,15.211
  Top Layer w0.4: CN1.7@0.172,15.211 R12.1
NetCN1_8: CN1.8 R13.1 | length 1.3
  Top Layer w0.3: CN1.8@0.202,12.711 CN1.8@0.204,12.708
  Top Layer w0.4: CN1.8@0.204,12.708 R13.1
NetCN1_9: CN1.9 R14.1 | length 1.2
  Top Layer w0.3: CN1.9@0.304,10.144 CN1.9@0.313,10.134
  Top Layer w0.4: CN1.9@0.313,10.134 R14.1
NetCN1_10: CN1.10 R15.1 | length 1.3
  Top Layer w0.3: CN1.10@0.174,7.586 CN1.10@0.181,7.593
  Top Layer w0.4: CN1.10@0.181,7.593 R15.1
NetCN1_11: CN1.11 R16.1 | length 1.4
  Top Layer w0.3: CN1.11@0.063,5.047 CN1.11@0.072,5.056
  Top Layer w0.4: CN1.11@0.072,5.056 R16.1
NetCN1_12: CN1.12 R17.1 | length 1.4
  Top Layer w0.25: R17.1@1.485,2.582 R17.1
  Top Layer w0.4: CN1.12@0.044,2.582 R17.1@1.485,2.582
NetCN2_1: CN2.1 R20.1 | length 1.6
  Top Layer w0.4: CN2.1@2.521,-2.618 R20.1@2.521,-0.983
NetCN2_4: CN2.4 R21.1 | length 1.6
  Top Layer w0.4: CN2.4@10.143,-2.573 10.159,-2.556 R21.1
NetCN2_5: CN2.5 R28.1 | length 1.5
  Top Layer w0.4: CN2.5@12.72,-2.478 R28.1@12.72,-0.98
NetCN2_7: CN2.7 R27.1 | length 1.5
  Top Layer w0.4: R27.1 17.792,-2.469 CN2.7@17.834,-2.511
NetCN3_2: CN3.2 R26.2 | length 1.4
  Top Layer w0.4: R26.2@18.984,2.515 20.342,2.515 CN3.2@20.351,2.523
NetCN3_3: CN3.3 R7.2 | length 1.6
  Top Layer w0.4: R7.2 20.396,5.071 CN3.3@20.413,5.054
NetCN3_4: CN3.4 R6.2 | length 1.7
  Top Layer w0.4: R6.2 19.965,7.88 CN3.4@20.347,7.499
NetCN3_5: CN3.5 R5.2 | length 1.6
  Top Layer w0.4: R5.2 19.948,9.877 CN3.5@20.281,10.21
NetCN3_8: CN3.8 R4.2 | length 1.6
  Top Layer w0.25: CN3.8@20.292,17.717 CN3.8@20.33,17.755
  Top Layer w0.4: R4.2 CN3.8@20.292,17.717
NetCN3_9: CN3.9 R3.2 | length 1.5
  Top Layer w0.25: CN3.9@20.165,20.229 CN3.9@20.199,20.263
  Top Layer w0.4: R3.2 CN3.9@20.165,20.229
NetCN3_10: CN3.10 R2.2 | length 1.6
  Top Layer w0.25: CN3.10@20.223,22.947 CN3.10@20.299,22.872
  Top Layer w0.4: R2.2 CN3.10@20.223,22.947
NetCN3_11: CN3.11 R1.2 | length 1.6
  Top Layer w0.25: CN3.11@20.352,25.426 CN3.11@20.368,25.442
  Top Layer w0.4: R1.2 CN3.11@20.352,25.426
NetR22_1: R22.1 R31.2 U2.13 | length 2.4
  Top Layer w0.3: R31.2 9.226,18.068 R22.1@9.249,18.045 ; R22.1@9.348,18.11 9.348,18.291 U2.13@10.381,19.323
NetR23_1: R23.1 R32.1 U2.14 | length 2.4
  Top Layer w0.3: U2.14@11.651,19.323 R23.1@12.745,18.229 ; R23.1 13.639,18.073 R32.1@13.667,18.101
Red_LED_U5: R28.2 U1.K13 | length 12.6
  Top Layer w0.15: R28.2@13.298,-1.014 13.397,-1.112 v1(13.835,-1.112) ; U1.K13 15.272,6.568 16.163,6.568 16.32,6.411 v1(16.401,6.411)
  Bottom Layer w0.15: v1(13.835,-1.112) 13.893,-1.055 14.106,-1.055 16.401,1.239 v1(16.401,6.411)
RSTN: R20.2 U1.H3 | length 12.9
  Top Layer w0.15: R20.2 3.128,-0.996 3.128,-0.397 v1@3.147,-0.377
  Internal 1 w0.15: v1(3.149,-0.384) 2.789,-0.024 2.789,3.328 8.178,8.717 8.423,8.717 8.625,8.919 8.625,8.92 8.763,9.058 v2(8.781,9.058)
SPI_CLK_U5: R7.1 U1.K4 U2.28 | length 52.3
  Top Layer w0.15: U2.28@10.381,30.754 U2.28@10.412,30.784 ; v1(17.887,4.684) 17.912,4.684 18.124,4.896 18.14,4.896 18.265,5.021 R7.1
  Top Layer w0.25: v1(10.381,30.015) U2.28@10.381,30.754
  Internal 1 w0.15: v2(9.277,8.061) 9.433,7.905 9.433,0.722 v1(9.987,0.168)
  Internal 2 w0.15: v1@9.961,0.188 17.215,0.188 17.887,0.859 17.887,4.726 17.841,4.772 17.841,18.884 17.69,19.035 17.69,26.684 14.796,29.577 10.819,29.577 v1(10.381,30.015)
SPI_CS_U5: R1.1 U1.J10 U2.24 | length 29.7
  Top Layer w0.2: U2.24@15.461,29.483 15.462,29.483 15.787,29.158 15.987,29.158 18.446,26.699 18.446,26.543 18.542,26.447 18.542,26.222 18.581,26.183 18.581,26.126 18.671,26.036 R1.1@18.727,26.036
  Internal 1 w0.15: v2(12.279,8.56) 13.419,7.42 15.807,7.42 16.933,8.546 16.933,14.305 16.347,14.891 16.347,24.39 18.452,26.495 v1(18.494,26.495)
"SPI_MISO_U5 / JTDO": R6.1 U1.N4 U2.29 | length 57.6
  Top Layer w0.15: v2(9.019,6.132) 9.043,6.132 9.259,6.348 U1.N4@9.259,6.556 ; U2.29@9.111,30.753 9.139,30.782 U2.29@9.174,30.817
  Top Layer w0.25: v1(9.139,29.961) U2.29@9.139,30.782 ; R6.1@18.841,7.268 18.879,7.23 18.879,6.796 v1(18.917,6.758)
  Internal 1 w0.15: v1(8.817,0.163) 8.814,0.166 8.814,5.927 v2(9.019,6.132)
  Internal 2 w0.15: v1(8.817,0.163) 9.643,-0.662 18.092,-0.662 18.917,0.163 v1@18.917,6.748 ; v1(9.139,29.961) 9.676,30.498 16.312,30.498 18.901,27.909 18.901,26.682 18.914,26.669 18.914,18.611 18.901,18.598 18.901,13.767 18.917,13.751 v1(18.917,6.758)
SPI_MOSI_U5: R26.1 U1.J5 U2.27 | length 48.5
  Top Layer w0.15: v1(16.957,1.867) 16.957,1.948 17.52,2.511 18.25,2.511 R26.1@18.254,2.515
  Top Layer w0.25: v1(11.62,29.066) 11.623,29.07 U2.27@11.623,30.772
  Internal 1 w0.15: v2(9.784,8.56) 9.811,8.56 9.861,8.51 9.872,8.51 10.038,8.344 10.038,5.019 10.133,4.924 10.133,1.76 10.812,1.081 v1(10.812,1.038)
  Internal 2 w0.15: v1(10.812,1.038) 10.87,0.981 11.019,0.981 11.05,0.949 16.013,0.949 16.944,1.88 16.944,25.886 14.162,28.668 12.018,28.668 v1(11.62,29.066)
SWCLK: R13.2 U1.C10 | length 17.2
  Top Layer w0.15: R13.2 2.064,13.674 3.144,14.754 3.551,15.161 3.881,15.161 v1(3.884,15.164)
  Internal 1 w0.15: v1(3.884,15.164) 4.554,15.164 4.734,15.344 12.935,15.344 13.341,14.938 13.341,12.149 12.913,11.721 12.43,11.721 v2(12.275,11.565)
SWDIO: R12.2 U1.F12 | length 17.6
  Top Layer w0.15: R12.2 2.045,15.261 2.17,15.386 2.22,15.386 2.475,15.641 v1(4.436,15.641)
  Internal 1 w0.15: v1(4.436,15.641) 13.107,15.641 13.702,15.045 13.702,11.535 12.931,10.764 12.931,10.414 v2(13.28,10.065)
USER_Buttom_U5: R15.2 U1.E3 | length 12.6
  Top Layer w0.15: v1(2.011,8.366) 2.011,8.285 2.069,8.227 R15.2
  Internal 1 w0.15: v1(2.011,8.366) 2.011,11.989 2.598,12.576 6.27,12.576 6.953,11.893 7.359,11.893 7.784,11.467 7.909,11.467 7.929,11.447 8.527,11.447 8.775,11.2 v2(8.775,10.56)
VCP1_RX: R16.2 U1.F11 | length 18.9
  Top Layer w0.15: R16.2 2.073,5.07 2.073,5.574 v1@2.092,5.594
  Internal 1 w0.15: v1@2.079,5.587 2.541,6.049 2.541,11.951 2.871,12.281 6.131,12.281 7.297,11.115 8.279,11.115 8.455,10.94 8.455,10.427 8.642,10.24 8.907,10.24 9.095,10.427 12.411,10.427 v2(12.774,10.065)
  other v1: 2.086,5.601
VCP1_TX: R17.2 U1.G11 | length 17.3
  Top Layer w0.15: R17.2 2.102,2.593 2.102,3.159 v1@2.121,3.178
  Internal 1 w0.15: v1(2.116,3.175) 2.116,5.037 2.811,5.731 2.811,8.787 3.538,9.514 7.315,9.514 7.318,9.517 7.517,9.517 7.682,9.682 10.172,9.682 10.601,10.111 12.232,10.111 v2(12.778,9.566)
VDD33: C10.2 CN3.7 R33.2 U2.16 | length 8.8
  Top Layer w0.4: U2.16@14.191,19.323 14.416,19.098 14.649,19.098 15.034,18.712 15.034,18.7 15.468,18.266 15.468,18.21 15.479,18.199 15.548,18.199 16.119,18.199 ; R33.2@16.647,18.864 16.549,18.864 16.47,18.784 16.47,18.549 16.119,18.199 ; CN3.7 20.265,15.295 19.354,15.295 16.45,18.199 16.119,18.199
VDD_IO1: C8.1 CN1.5 R29.2 U2.9 | length 11.9
  Top Layer w0.3: v1@1.398,23.976 1.563,23.811 1.922,23.811 R29.2
  Top Layer w0.5: CN1.5 v1@1.361,20.32 ; v1(1.37,20.328) 3.474,18.224 C8.1@5.15,18.224 ; C8.1 5.171,19.209 U2.9@5.257,19.295
  Bottom Layer w0.3: v1@1.336,24.06 1.722,23.674 1.722,20.681 v1(1.37,20.328)
  other v1: 1.328,24.043
VDD_IO2: C9.1 CN3.13 U2.25 | length 6
  Top Layer w0.5: U2.25 14.344,30.602 14.537,30.602 14.637,30.503 C9.1@16.553,30.503 ; C9.1@16.813,30.48 CN3.13
VDD_MCU: C17.2 C18.2 C19.2 C20.2 C21.2 C22.2 C23.2 C24.2 C25.2 C26.2 C27.2 C29.2 C30.2 C31.2 C33.2 C34.2 C35.2 C36.2 C38.2 C39.2 C41.2 C42.2 C43.2 CN2.3 U1.A3 U1.A6 U1.A8 U1.A11 U1.B1 U1.C1 U1.D13 U1.E13 U1.G1 U1.H12 U1.J13 U1.L1 U1.L2 U1.N3 U1.N7 U1.N10 U1.N12 | length 111.9
  Top Layer w0.2: C34.2@5.777,5.772 5.932,5.927 6.12,5.927 7.755,7.562 U1.L1 ; C39.2@6.114,12.979 7.501,11.591 7.678,11.591 7.688,11.581 7.759,11.581 U1.C1 ; C27.2 7.08,13.707 7.301,13.486 7.301,12.309 7.488,12.122 7.691,12.122 7.751,12.062 U1.B1 ; U1.N3 8.778,6.535 8.642,6.399 8.642,5.549 C21.2 ; 10.778,6.282 U1.N7 ; 12.267,6.26 12.278,6.272 U1.N10 ; U1.N12 13.278,6.535 13.418,6.394 13.418,6.328 ; U1.J13 13.805,8.562 13.858,8.509 14.002,8.509 14.015,8.495 ; U1.D13 13.805,11.062 14.264,11.521 ; U1.E13@13.795,10.581 13.795,10.572 13.824,10.543 13.833,10.543 13.853,10.523 13.985,10.523 14.077,10.431
  Top Layer w0.25: C33.2 5.008,4.203 5.008,4.361 5.021,4.374 5.021,5.232 5.432,5.642 5.653,5.642 C34.2@5.777,5.765 ; C22.2@6.519,9.917 6.539,9.937 v1(7.16,9.937) 7.548,9.548 U1.G1@7.74,9.548 ; v1(8.765,13.097) 8.767,13.099 8.767,13.592 C20.2@8.806,13.631 ; U1.A3 v1@8.778,13.067 ; v1(10.266,13.112) 10.304,13.15 10.304,13.579 C31.2@10.414,13.689 ; U1.A6 v1@10.278,13.058 ; U1.A8 11.278,13.694 C25.2@11.282,13.698 ; U1.A11@12.794,12.566 12.787,12.566 12.768,12.585 12.768,12.592 12.764,12.597 v1(12.764,13.168) 12.761,13.17 12.761,13.584 C26.2@12.862,13.685 ; 14.015,8.495 14.112,8.495 v1@14.275,8.331 ; 14.077,10.431 14.123,10.384 v1@14.204,10.384 ; 14.264,11.521 v1@14.797,11.521 ; v1(14.358,8.284) 14.651,7.99 C24.2@14.686,7.99 ; v1(14.358,10.284) 14.781,10.708 14.824,10.708 C38.2@14.922,10.806 ; v1(14.798,11.492) 14.836,11.53 14.836,12.106 C19.2@14.87,12.14
  Top Layer w0.3: v1(10.508,5.953) 10.508,5.993 10.583,6.068 10.583,6.087 10.778,6.282 ; C43.2 12.121,5.461 C43.2@12.226,5.566 ; v1@12.226,5.931 v1(12.255,5.96) ; 13.418,6.328 13.604,6.142 14.136,6.142 14.268,6.01 14.28,6.01 v1@14.326,5.963 ; v1(14.864,9.435) 14.893,9.464 14.893,9.956 C30.2@14.891,9.958
  Top Layer w0.4: C33.2@4.847,4.071 4.884,4.034 4.884,3.473 v1(4.89,3.466) ; C41.2 6.045,13.946 6.045,13.148 C39.2@6.065,13.128 ; C41.2@6.079,13.888 6.093,13.902 6.093,13.959 C41.2@6.178,13.959 ; 6.308,14.015 v1@6.379,13.943 ; v1(6.49,13.834) 6.488,13.834 v1@6.379,13.943 ; v1(6.878,1.404) 6.888,1.414 7.389,1.414 7.421,1.445 C17.2@7.421,1.463 ; C27.2@7.053,13.68 7.053,13.784 7.025,13.812 6.51,13.812 v1@6.379,13.943 ; C35.2 7.42,4.073 C36.2@7.42,4.891 ; v1(7.42,3.45) C35.2@7.42,4.068 ; C36.2 7.437,4.906 v2@7.437,5.257 ; v1(8.285,5.465) 8.294,5.456 8.706,5.456 8.756,5.406 C21.2 ; C23.2 9.734,5.441 9.996,5.441 v1(10.508,5.953) ; C43.2@12.226,5.566 v1@12.226,5.931 ; v1(12.255,5.96) v1@12.255,6.169 ; v1@14.393,5.95 14.404,5.939 14.934,5.939 C18.2 ; v1(15.656,4.592) 15.669,4.592 15.732,4.529 16.113,4.529 16.147,4.495 C29.2@16.147,4.445
  Internal 1 w0.15: v2(7.449,5.348) 7.449,6.735 v2(8.277,7.563)
  Internal 1 w0.25: v2(13.277,9.059) 13.575,9.059 13.97,9.454 14.845,9.454 v1(14.864,9.435)
  Internal 2 w0.4: v1(4.89,3.466) 6.757,1.6 ; v1@6.878,1.368 5.517,1.368 4.011,2.874 ; 6.878,1.721 6.878,2.907 v1(7.42,3.45) ; v1@6.878,1.57 6.878,1.721 9.45,4.294 9.45,4.923 9.456,4.929 ; v1@7.177,9.989 7.169,9.982 7.169,9.946 v1(7.16,9.937) 7.16,9.923 7.177,9.906 7.177,7.513 4.011,4.348 4.011,2.874 ; CN2.3@7.636,-2.502 7.636,-1.017 7.271,-0.652 7.271,1.012 v1(6.878,1.404) 7.162,1.688 8.496,1.688 8.522,1.714 8.708,1.714 10.742,3.749 10.742,4.089 v1(10.752,4.099) ; v1@8.298,5.465 8.308,5.456 8.643,5.456 9.17,4.929 9.456,4.929 ; v1(8.765,13.097) 7.228,13.097 v1(6.49,13.834) 6.08,14.245 3.587,14.245 2.631,13.289 2.631,12.01 2.63,12.009 2.63,11.558 2.631,11.557 2.631,4.254 4.011,2.874 ; v1(10.266,13.112) 10.266,13.54 10.595,13.869 11.48,13.869 ; v1@10.485,5.943 10.469,5.928 10.455,5.928 9.456,4.929 ; v1@10.775,4.089 10.844,4.02 15.199,4.02 15.646,4.467 15.646,4.582 v1(15.656,4.592) 15.646,4.601 15.646,4.666 v1@14.436,5.876 ; v1@10.791,4.124 12.258,5.591 12.258,5.958 v1(12.255,5.96) ; v1(11.26,13.116) 11.26,13.13 11.48,13.35 11.48,13.869 ; v1@12.754,13.188 12.754,13.869 ; v1(14.358,8.284) 14.781,8.284 14.808,8.31 ; v1(14.358,10.284) 14.364,10.29 14.714,10.29 ; v1@14.523,5.944 14.808,6.228 14.808,8.31 ; v1@14.788,11.538 14.788,12.59 13.509,13.869 12.754,13.869 ; v1@14.789,11.496 v1@14.789,11.537 ; v1@14.808,11.463 14.808,9.505 14.864,9.448 v1(14.864,9.435) 14.864,9.421 14.808,9.365 14.808,8.31 ; 11.48,13.869 12.754,13.869
  other v1: 14.396,5.935
pads on no net: CART-1.1 U1.A1 U1.A2 U1.A5 U1.A7 U1.A9 U1.A10 U1.A12 U1.A13 U1.B3 U1.B5 U1.B6 U1.B7 U1.B9 U1.B10 U1.B12 U1.B13 U1.C2 U1.C3 U1.C4 U1.C6 U1.C7 U1.C8 U1.C9 U1.C11 U1.C12 U1.C13 U1.D2 U1.D3 U1.D4 U1.D5 U1.D6 U1.D7 U1.D8 U1.D9 U1.D10 U1.D11 U1.D12 U1.E2 U1.E4 U1.E5 U1.E6 U1.E7 U1.E8 U1.E9 U1.E10 U1.E11 U1.F1 U1.F3 U1.F4 U1.F5 U1.F6 U1.F7 U1.F8 U1.F9 U1.F10 U1.F13 U1.G2 U1.G3 U1.G4 U1.G5 U1.G6 U1.G7 U1.G9 U1.G10 U1.G12 U1.G13 U1.H4 U1.H5 U1.H6 U1.H7 U1.H8 U1.H10 U1.H11 U1.H13 U1.J2 U1.J3 U1.J4 U1.J6 U1.J8 U1.J9 U1.K1 U1.K3 U1.K5 U1.K6 U1.K7 U1.K8 U1.K9 U1.K10 U1.K11 U1.K12 U1.L3 U1.L4 U1.L5 U1.L6 U1.L7 U1.L9 U1.L10 U1.L11 U1.L12 U1.L13 U1.M1 U1.M4 U1.M5 U1.M6 U1.M9 U1.M12 U1.M13 U1.N1 U1.N2 U1.N5 U1.N6 U1.N8 U1.N13 U2.5 U2.6 U2.7 U2.8 U2.11 U2.12 U2.19 U2.20 U2.31
copper on no net: | length 1348.4
  Top Layer w0.381: -0.005,81.549 10.406,81.549 34.022,81.549 55.86,81.549 72.366,81.549 86.84,81.549 ; -0.005,84.597 10.406,84.597 34.022,84.597 55.86,84.597 72.366,84.597 86.84,84.597 ; -0.005,87.645 10.406,87.645 34.022,87.645 55.86,87.645 72.366,87.645 86.84,87.645 ; -0.005,90.693 10.406,90.693 34.022,90.693 55.86,90.693 72.366,90.693 86.84,90.693 ; -0.005,93.741 10.406,93.741 34.022,93.741 55.86,93.741 72.366,93.741 86.84,93.741 ; -0.005,96.789 10.406,96.789 34.022,96.789 55.86,96.789 72.366,96.789 86.84,96.789 ; -0.005,99.837 10.406,99.837 34.022,99.837 55.86,99.837 72.366,99.837 86.84,99.837 ; -0.005,102.885 10.406,102.885 34.022,102.885 55.86,102.885 72.366,102.885 86.84,102.885 ; -0.005,105.933 10.406,105.933 34.022,105.933 55.86,105.933 72.366,105.933 86.84,105.933 ; -0.005,108.981 10.406,108.981 34.022,108.981 55.86,108.981 72.366,108.981 86.84,108.981 ; -0.005,112.029 86.84,112.029 ; 10.406,115.077 10.406,78.501 ; 34.022,115.077 34.022,78.501 ; 55.86,115.077 55.86,78.501 ; 72.366,115.077 72.366,78.501 ; 10.406,78.501 34.022,78.501 ; 10.406,78.501 -0.005,78.501 -0.005,115.077 86.84,115.077 86.84,78.501 72.366,78.501 ; 34.022,78.501 55.86,78.501 ; 55.86,78.501 72.366,78.501

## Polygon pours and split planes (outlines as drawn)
GND on Internal 2 "GND_L03_P003" (solid, pour order 3): -0.062,31.489 -0.059,31.492 20.259,31.492 20.259,-1.285 18.972,-2.572 1.201,-2.572 -0.071,-1.3 -0.063,-1.292 -0.063,31.49
GND on Internal 1 "GND_L02_P001" (solid, pour order 1): -0.014,31.422 -0.011,31.425 20.307,31.425 20.307,-1.352 19.02,-2.639 1.249,-2.639 -0.023,-1.367 -0.015,-1.359 -0.015,31.423
GND on Bottom Layer "GND_L04_P002" (solid, pour order 2): 0.002,31.509 0.005,31.512 20.323,31.512 20.323,-1.265 19.036,-2.552 1.265,-2.552 -0.007,-1.28 0.001,-1.272 0.001,31.51
GND on Top Layer "GND_L01_P000" (solid, pour order 0): 0.024,31.484 0.027,31.487 20.345,31.487 20.345,-1.29 19.058,-2.577 1.287,-2.577 0.015,-1.305 0.023,-1.296 0.023,31.486

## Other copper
Top Layer:
  region net AGND: 5.47,3.779 5.475,3.784 5.475,5.192 6.224,5.192 6.702,6.1 7.018,6.1 7.119,5.999 7.119,5.678 7.023,5.581 6.953,5.581 6.782,5.411 6.782,3.272 6.491,2.98 5.812,2.98 5.48,3.312 5.48,3.779
  text "Layer" at 1.773,112.791 h1.52
  text "Name" at 12.184,112.791 h1.52
  text "Material" at 35.8,112.791 h1.52
  text "Thickness" at 57.638,112.791 h1.52
  text "Constant" at 74.144,112.791 h1.52
  text "Top Overlay" at 12.184,109.743 h1.52
  text "Top Solder" at 12.184,106.695 h1.52
  text "Solder Resist" at 35.8,106.695 h1.52
  text "0.018mm" at 57.638,106.695 h1.52
  text "3.2" at 74.144,106.695 h1.52
  text "1" at 1.773,103.647 h1.52
  text "Top Layer" at 12.184,103.647 h1.52
  text "0.041mm" at 57.638,103.647 h1.52
  text "Dielectric 1" at 12.184,100.599 h1.52
  text "FR-4" at 35.8,100.599 h1.52
  text "0.076mm" at 57.638,100.599 h1.52
  text "3.7" at 74.144,100.599 h1.52
  text "2" at 1.773,97.551 h1.52
  text "Internal 1" at 12.184,97.551 h1.52
  text "0.030mm" at 57.638,97.551 h1.52
  text "Dielectric 3" at 12.184,94.503 h1.52
  text "0.940mm" at 57.638,94.503 h1.52
  text "4.5" at 74.144,94.503 h1.52
  text "3" at 1.773,91.455 h1.52
  text "Internal 2" at 12.184,91.455 h1.52
  text "0.030mm" at 57.638,91.455 h1.52
  text "Dielectric 2" at 12.184,88.407 h1.52
  text "0.076mm" at 57.638,88.407 h1.52
  text "3.7" at 74.144,88.407 h1.52
  text "4" at 1.773,85.359 h1.52
  text "Bottom Layer" at 12.184,85.359 h1.52
  text "0.041mm" at 57.638,85.359 h1.52
  text "Bottom Solder" at 12.184,82.311 h1.52
  text "Solder Resist" at 35.8,82.311 h1.52
  text "0.018mm" at 57.638,82.311 h1.52
  text "4.2" at 74.144,82.311 h1.52
  text "Bottom Overlay" at 12.184,79.263 h1.52

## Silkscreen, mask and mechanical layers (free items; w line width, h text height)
Top Overlay:
  lines w0.2: 0.99,31.329 0.99,-1.615 19.457,-1.615 19.457,-1.595 19.462,-1.595 19.462,31.359
  text "ST67W611M" at 7.949,15.035 h1
  text "B2413" at 9.065,0.557 h1.2
Bottom Overlay:
  text "J" at 6.531,17.327 h10
M1-Board Shape:
  lines w0.2: 0,31.46 20.329,31.46 ; 0,31.517 0,-1.27 1.27,-2.54 19.05,-2.54 20.32,-1.27 20.32,31.517
Drill Drawing:
  lines w0.254: 1.443,66.436 3.1,66.436 2.271,64.779 1.443,66.436 ; 1.443,68.507 3.1,68.507 3.1,70.164 1.443,70.164 1.443,68.507
  lines w0.381: -0.045,63.66 206.884,63.66 ; -0.045,71.117 206.884,71.117 ; 9.535,59.932 9.535,74.845 ; 18.334,59.932 18.334,74.845 ; 33.882,59.932 33.882,74.845 ; 41.311,59.932 41.311,74.845 ; 52.125,59.932 52.125,74.845 ; 72.624,59.932 72.624,74.845 ; 81.486,59.932 81.486,74.845 ; 97.777,59.932 97.777,74.845 ; 123.763,59.932 123.763,74.845 ; 135.389,59.932 135.389,74.845 ; 153.468,59.932 153.468,74.845 ; 171.061,59.932 171.061,74.845 ; 186.611,59.932 186.611,74.845 ; -0.045,59.932 206.884,59.932 206.884,74.845 -0.045,74.845 -0.045,59.932
  text "Symbol" at 2.192,72.235 h2.16
  text "Count" at 10.654,72.235 h2.16
  text "Hole Size" at 19.452,72.235 h2.16
  text "Plated" at 35.001,72.235 h2.16
  text "Hole Type" at 42.429,72.235 h2.16
  text "Drill Layer Pair" at 53.244,72.235 h2.16
  text "Via/Pad" at 73.743,72.235 h2.16
  text "Pad Shape" at 82.604,72.235 h2.16
  text "Template" at 98.896,72.235 h2.16
  text "Description" at 124.882,72.235 h2.16
  text "Hole Tolerance (+)" at 136.508,72.235 h2.16
  text "Hole Tolerance (-)" at 154.587,72.235 h2.16
  text "Hole Length" at 172.18,72.235 h2.16
  text "Routed Path Length" at 187.73,72.235 h2.16
  text "33" at 10.654,68.507 h1.8
  text "39.37mil (1.00mm)" at 19.452,68.507 h1.8
  text "PTH" at 35.001,68.507 h1.8
  text "Slot" at 42.429,68.507 h1.8
  text "Top Layer - Bottom Layer" at 53.244,68.507 h1.8
  text "Pad" at 73.743,68.507 h1.8
  text "Rounded Rectangle" at 82.604,68.507 h1.8
  text "r200_120h100_150r50m210_130" at 98.896,68.507 h1.8
  text "59.06mil (1.50mm)" at 172.18,68.507 h1.8
  text "19.69mil (0.50mm)" at 187.73,68.507 h1.8
  text "211" at 10.654,64.779 h1.8
  text "7.87mil (0.20mm)" at 19.452,64.779 h1.8
  text "PTH" at 35.001,64.779 h1.8
  text "Round" at 42.429,64.779 h1.8
  text "Top Layer - Bottom Layer" at 53.244,64.779 h1.8
  text "Via" at 73.743,64.779 h1.8
  text "Rounded" at 82.604,64.779 h1.8
  text "v45h20m0mx0" at 98.896,64.779 h1.8
  text "-" at 172.18,64.779 h1.8
  text "-" at 187.73,64.779 h1.8
  text "244 Total" at 10.654,61.051 h1.8
  text "Slot definitions :" at 2.192,58.441 h1.8
  text "Routed Path Length" at 14.478,58.441 h1.8
  text "= Calculated from tool start centre position to tool end centre position." at 29.697,58.441 h1.8
  text "Hole Length" at 14.478,56.95 h1.8
  text "= Routed Path Length + Tool Size = Slot length as defined in the PCB layout" at 24.047,56.95 h1.8

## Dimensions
0,-1.27 to 20.32,-1.27 on M3-Top Dimensions
20.329,31.46 to 19.05,-2.54 on M3-Top Dimensions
